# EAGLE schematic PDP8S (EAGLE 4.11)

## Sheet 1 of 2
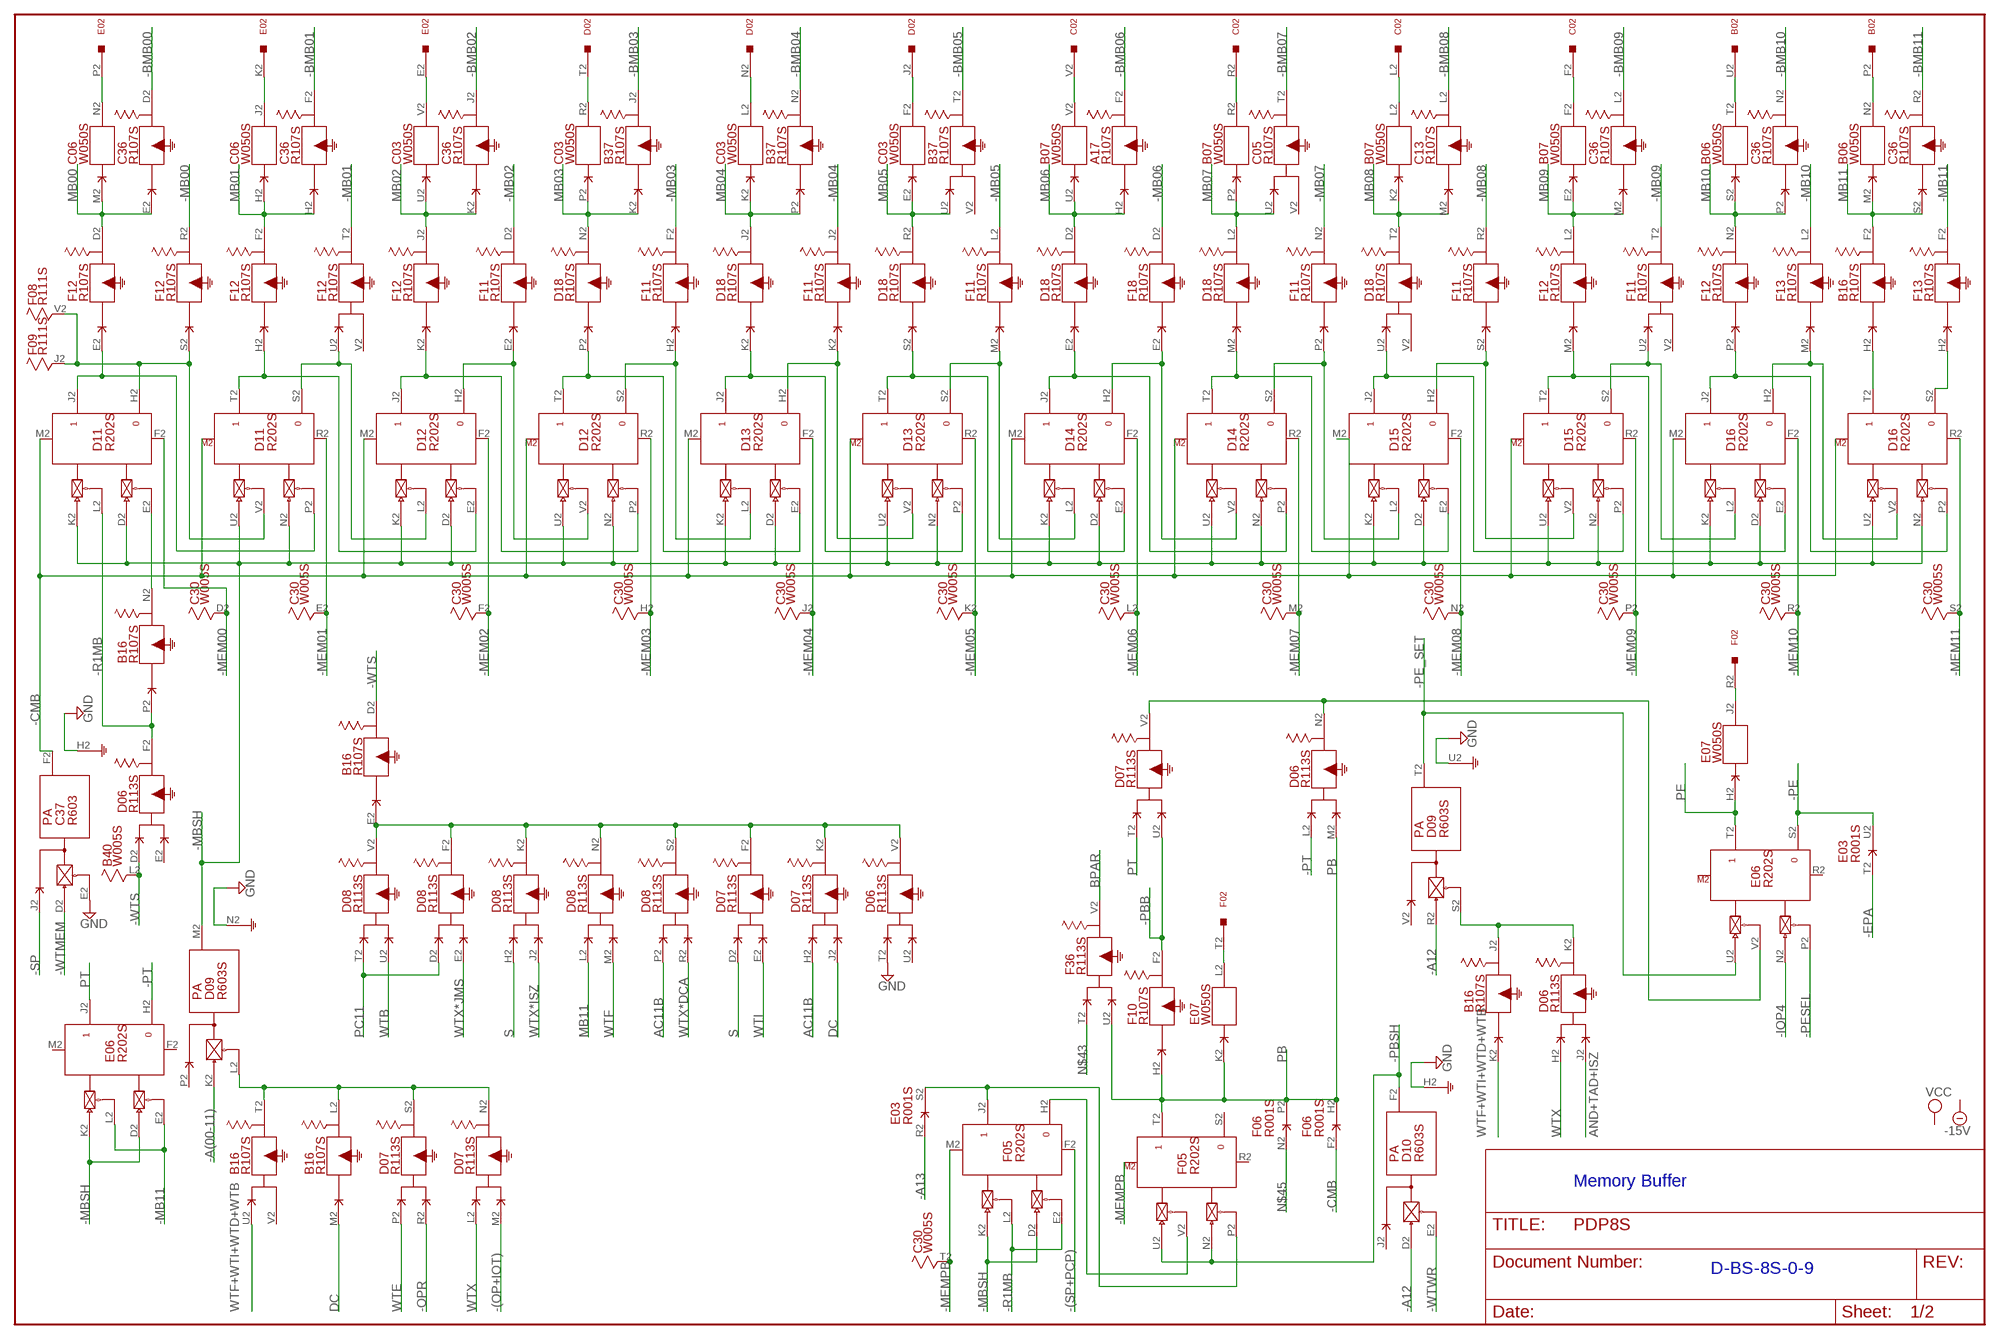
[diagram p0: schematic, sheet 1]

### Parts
A17  R107S  [H807S]
B02  W023S  [H807S]
B06  W050S  [H807S]
B07  W050S  [H807S]
B16  R107S  [H807S]
B37  R107S  [H807S]
B40  W005S  [H807S]
C02  W023S  [H807S]
C03  W050S  [H807S]
C05  R107S  [H807S]
C06  W050S  [H807S]
C13  R107S  [H807S]
C30  W005S  [H807S]
C36  R107S  [H807S]
C37  R603  [H807]
D02  W023S  [H807S]
D06  R113S  [H807S]
D07  R113S  [H807S]
D08  R113S  [H807S]
D09  R603S  [H807S]
D10  R603S  [H807S]
D11  R202S  [H807S]
D12  R202S  [H807S]
D13  R202S  [H807S]
D14  R202S  [H807S]
D15  R202S  [H807S]
D16  R202S  [H807S]
D18  R107S  [H807S]
E02  W023S  [H807S]
E03  R001S  [H807S]
E06  R202S  [H807S]
E07  W050S  [H807S]
F02  W023S  [H807S]
F05  R202S  [H807S]
F06  R001S  [H807S]
F08  R111S  [H807S]
F09  R111S  [H807S]
F10  R107S  [H807S]
F11  R107S  [H807S]
F12  R107S  [H807S]
F13  R107S  [H807S]
F18  R107S  [H807S]
F36  R113S  [H807S]

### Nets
-(OP+IOT): D07.M2(N:I$2)
-(SP+PCP): F05.F2(J:RESET)
-A12: D09.R2(T:PU0) D10.D2(F:PU0)
-A13: E03.R2(S:D)
-A(00-11): D09.K2(M:PU0)
-BMB00: C36.D2(D:O$1)
-BMB01: C36.F2(F:O$1)
-BMB02: C36.J2(J:O$1)
-BMB03: B37.J2(J:O$1)
-BMB04: B37.N2(N:O$1)
-BMB05: B37.T2(T:O$1)
-BMB06: A17.F2(F:O$1)
-BMB07: C05.T2(T:O$1)
-BMB08: C13.L2(L:O$1)
-BMB09: C36.L2(L:O$1)
-BMB10: C36.N2(N:O$1)
-BMB11: C36.R2(R:O$1)
-CMB: C37.F2(F:O) D11.M2(J:SET) D12.M2(J:SET) D13.M2(J:SET) D14.M2(J:SET) D15.M2(J:SET) D16.M2(J:SET) F06.F2(H:D)
-EPA: E03.T2(U:D)
-IOP4: E06.N2(T:PU0)
-MB00: F12.R2(R:O$1)
-MB01: F12.T2(T:O$1)
-MB02: F11.D2(D:O$1)
-MB03: F11.F2(F:O$1)
-MB04: F11.J2(J:O$1)
-MB05: F11.L2(L:O$1)
-MB06: F18.D2(D:O$1)
-MB07: F11.N2(N:O$1)
-MB08: F11.R2(R:O$1)
-MB09: F11.T2(T:O$1)
-MB10: F13.L2(L:O$1)
-MB11: E06.E2(J:EN0) E06.L2(J:EN1) F13.F2(F:O$1)
-MBSH: D09.M2(M:O) D11.D2(J:PU0) D11.K2(J:PU1) D11.N2(T:PU0) D11.U2(T:PU1) D12.D2(J:PU0) D12.K2(J:PU1) D12.N2(T:PU0) D12.U2(T:PU1) D13.D2(J:PU0) D13.K2(J:PU1) D13.N2(T:PU0) D13.U2(T:PU1) D14.D2(J:PU0) D14.K2(J:PU1) D14.N2(T:PU0) D14.U2(T:PU1) D15.D2(J:PU0) D15.K2(J:PU1) D15.N2(T:PU0) D15.U2(T:PU1) D16.D2(J:PU0) D16.K2(J:PU1) D16.N2(T:PU0) D16.U2(T:PU1) E06.D2(J:PU0) E06.K2(J:PU1) F05.D2(J:PU0) F05.K2(J:PU1)
-MEM00: C30.D2 D11.F2(J:RESET)
-MEM01: C30.E2 D11.R2(T:RESET)
-MEM02: C30.F2 D12.F2(J:RESET)
-MEM03: C30.H2 D12.R2(T:RESET)
-MEM04: C30.J2 D13.F2(J:RESET)
-MEM05: C30.K2 D13.R2(T:RESET)
-MEM06: C30.L2 D14.F2(J:RESET)
-MEM07: C30.M2 D14.R2(T:RESET)
-MEM08: C30.N2 D15.F2(J:RESET)
-MEM09: C30.P2 D15.R2(T:RESET)
-MEM10: C30.R2 D16.F2(J:RESET)
-MEM11: C30.S2 D16.R2(T:RESET)
-MEMPB: C30.T2 F05.M2(J:SET)
-OPR: D07.R2(S:I$2)
-PBB: D07.U2(V:I$2) F10.F2(F:O$1)
-PBSH: D10.F2(F:O) F05.N2(T:PU0) F05.U2(T:PU1)
-PE: E03.U2(U:E) E06.S2
-PE_SET: D09.T2(T:O) E06.U2(T:PU1)
-PESEL: E06.P2(T:EN0)
-PT: D06.L2(N:I$1) E06.H2
-R1MB: B16.P2(N:I$1) D06.F2(F:O$1) D11.L2(J:EN1) F05.E2(J:EN0) F05.L2(J:EN1)
-SP: C37.J2(F:I$1)
-WTMEM: C37.D2(F:PU0)
-WTS: B16.D2(D:O$1) B40.L2 D06.D2(F:I$1)
-WTWR: D10.E2(F:EN0)
AC11B: D07.H2(K:I$1) D08.P2(S:I$1)
AND+TAD+ISZ: D06.J2(K:I$2)
BPAR: F36.V2(V:O$1)
DC: B16.M2(L:I$1) D07.J2(K:I$2)
GND [Supply]: C37.E2(F:EN0) C37.H2(F:G) D06.T2(V:I$1) D09.N2(M:G) D09.U2(T:G) D10.H2(F:G)
MB00: C06.M2(N:I$1) C36.E2(D:I$1) F12.D2(D:O$1)
MB01: C06.H2(J:I$1) C36.H2(F:I$1) F12.F2(F:O$1)
MB02: C03.U2(V:I$1) C36.K2(J:I$1) F12.J2(J:O$1)
MB03: B37.K2(J:I$1) C03.P2(R:I$1) D18.N2(N:O$1)
MB04: B37.P2(N:I$1) C03.K2(L:I$1) D18.J2(J:O$1)
MB05: B37.U2(T:I$1) C03.E2(F:I$1) D18.R2(R:O$1)
MB06: A17.H2(F:I$1) B07.U2(V:I$1) D18.D2(D:O$1)
MB07: B07.P2(R:I$1) C05.U2(T:I$1) D18.L2(L:O$1)
MB08: B07.K2(L:I$1) C13.M2(L:I$1) D18.T2(T:O$1)
MB09: B07.E2(F:I$1) C36.M2(L:I$1) F12.L2(L:O$1)
MB10: B06.S2(T:I$1) C36.P2(N:I$1) F12.N2(N:O$1)
MB11: B06.M2(N:I$1) B16.F2(F:O$1) C36.S2(R:I$1) D08.L2(N:I$1)
N$1: D11.J2 D11.P2(T:EN0) F12.E2(D:I$1)
N$2: C06.N2(N:O$1) E02.P2
N$3: D11.H2 D11.V2(T:EN1) F08.V2 F09.J2 F12.S2(R:I$1)
N$4: D11.T2 D12.E2(J:EN0) F12.H2(F:I$1)
N$5: B16.E2(D:I$1) D06.V2(V:O$1) D07.F2(F:O$1) D07.K2(K:O$1) D08.F2(F:O$1) D08.K2(K:O$1) D08.N2(N:O$1) D08.S2(S:O$1) D08.V2(V:O$1)
N$6: D12.J2 D12.P2(T:EN0) F12.K2(J:I$1)
N$7: D12.T2 D13.E2(J:EN0) D18.P2(N:I$1)
N$8: D13.J2 D13.P2(T:EN0) D18.K2(J:I$1)
N$9: D13.T2 D14.E2(J:EN0) D18.S2(R:I$1)
N$10: D14.J2 D14.P2(T:EN0) D18.E2(D:I$1)
N$11: D14.T2 D15.E2(J:EN0) D18.M2(L:I$1)
N$12: D15.J2 D15.P2(T:EN0) D18.U2(T:I$1)
N$13: D15.H2 D15.V2(T:EN1) F11.S2(R:I$1)
N$14: D14.S2 D15.L2(J:EN1) F11.P2(N:I$1)
N$15: D14.H2 D14.V2(T:EN1) F18.E2(D:I$1)
N$16: D13.S2 D14.L2(J:EN1) F11.M2(L:I$1)
N$17: D15.T2 D16.E2(J:EN0) F12.M2(L:I$1)
N$18: D15.S2 D16.L2(J:EN1) F11.U2(T:I$1)
N$19: D16.J2 D16.P2(T:EN0) F12.P2(N:I$1)
N$20: D13.H2 D13.V2(T:EN1) F11.K2(J:I$1)
N$21: D12.S2 D13.L2(J:EN1) F11.H2(F:I$1)
N$22: D12.H2 D12.V2(T:EN1) F11.E2(D:I$1)
N$23: D11.S2 D12.L2(J:EN1) F12.U2(T:I$1)
N$24: D16.H2 D16.V2(T:EN1) F13.M2(L:I$1)
N$25: B16.H2(F:I$1) D16.T2
N$26: D16.S2 F13.H2(F:I$1)
N$27: C06.J2(J:O$1) E02.K2
N$28: C03.V2(V:O$1) E02.E2
N$29: C03.R2(R:O$1) D02.T2
N$30: C03.L2(L:O$1) D02.N2
N$31: C03.F2(F:O$1) D02.J2
N$32: B07.V2(V:O$1) C02.V2
N$33: B07.R2(R:O$1) C02.R2
N$34: B07.L2(L:O$1) C02.L2
N$35: B07.F2(F:O$1) C02.F2
N$36: B02.U2 B06.T2(T:O$1)
N$37: B02.P2 B06.N2(N:O$1)
N$38: B16.L2(L:O$1) B16.T2(T:O$1) D07.N2(N:O$1) D07.S2(S:O$1) D09.L2(M:EN0)
N$39: B16.N2(N:O$1) D11.E2(J:EN0)
N$40: B16.J2(J:O$1) D06.K2(K:O$1) D09.S2(T:EN0)
N$41: E07.J2(J:O$1) F02.R2
N$42: D06.N2(N:O$1) D07.V2(V:O$1) E06.V2(T:EN1)
N$43: F36.T2(V:I$1)
N$44: E07.L2(L:O$1) F02.T2
N$45: F06.N2(P:D)
N$46: F05.H2 F05.V2(T:EN1)
N$47: E03.S2(S:E) F05.J2 F05.P2(T:EN0)
PB: D06.M2(N:I$2) E07.K2(L:I$1) F05.T2 F06.H2(H:E) F06.P2(P:E) F10.H2(F:I$1) F36.U2(V:I$2)
PC11: D08.D2(F:I$1) D08.T2(V:I$1)
PE: E06.T2 E07.H2(J:I$1)
PT: D07.T2(V:I$1) E06.J2
S: D07.D2(F:I$1) D08.H2(K:I$1)
WTB: D08.U2(V:I$2)
WTE: D07.P2(S:I$1)
WTF: D08.M2(N:I$2)
WTF+WTI+WTD+WTB: B16.K2(J:I$1) B16.U2(T:I$1)
WTI: D07.E2(F:I$2)
WTX: D06.H2(K:I$1) D07.L2(N:I$1)
WTX*DCA: D08.R2(S:I$2)
WTX*ISZ: D08.J2(K:I$2)
WTX*JMS: D08.E2(F:I$2)
Unconnected: A17.D2(D:O$1) A17.E2(D:I$1) A17.J2(J:O$1) A17.K2(J:I$1) A17.L2(L:O$1) A17.M2(L:I$1) A17.N2(N:O$1) A17.P2(N:I$1) A17.R2(R:O$1) A17.S2(R:I$1) A17.T2(T:O$1) A17.U2(T:I$1) A17.V2(T:I$2) B02.A2 B02.B2 B02.C2 B02.D2 B02.E2 B02.F2 B02.H2 B02.J2 B02.K2 B02.L2 B02.M2 B02.N2 B02.R2 B02.S2 B02.T2 B02.V2 B06.E2(F:I$1) B06.F2(F:O$1) B06.H2(J:I$1) B06.J2(J:O$1) B06.K2(L:I$1) B06.L2(L:O$1) B06.P2(R:I$1) B06.R2(R:O$1) B06.U2(V:I$1) B06.V2(V:O$1) B07.H2(J:I$1) B07.J2(J:O$1) B07.M2(N:I$1) B07.N2(N:O$1) B07.S2(T:I$1) B07.T2(T:O$1) B16.R2(R:O$1) B16.S2(R:I$1) B16.V2(T:I$2) B37.D2(D:O$1) B37.E2(D:I$1) B37.F2(F:O$1) B37.H2(F:I$1) B37.L2(L:O$1) B37.M2(L:I$1) B37.R2(R:O$1) B37.S2(R:I$1) B37.V2(T:I$2) B40.D2 B40.E2 B40.F2 B40.H2 B40.J2 B40.K2 B40.M2 B40.N2 B40.P2 B40.R2 B40.S2 B40.T2 B40.U2 B40.V2 C02.A2 C02.B2 C02.C2 C02.D2 C02.E2 C02.H2 C02.J2 C02.K2 C02.M2 C02.N2 C02.P2 C02.S2 C02.T2 C02.U2 C03.H2(J:I$1) C03.J2(J:O$1) C03.M2(N:I$1) C03.N2(N:O$1) C03.S2(T:I$1) C03.T2(T:O$1) C05.D2(D:O$1) C05.E2(D:I$1) C05.F2(F:O$1) C05.H2(F:I$1) C05.J2(J:O$1) C05.K2(J:I$1) C05.L2(L:O$1) C05.M2(L:I$1) C05.N2(N:O$1) C05.P2(N:I$1) C05.R2(R:O$1) C05.S2(R:I$1) C05.V2(T:I$2) C06.E2(F:I$1) C06.F2(F:O$1) C06.K2(L:I$1) C06.L2(L:O$1) C06.P2(R:I$1) C06.R2(R:O$1) C06.S2(T:I$1) C06.T2(T:O$1) C06.U2(V:I$1) C06.V2(V:O$1) C13.D2(D:O$1) C13.E2(D:I$1) C13.F2(F:O$1) C13.H2(F:I$1) C13.J2(J:O$1) C13.K2(J:I$1) C13.N2(N:O$1) C13.P2(N:I$1) C13.R2(R:O$1) C13.S2(R:I$1) C13.T2(T:O$1) C13.U2(T:I$1) C13.V2(T:I$2) C30.U2 C30.V2 C36.T2(T:O$1) C36.U2(T:I$1) C36.V2(T:I$2) C37.K2(M:PU0) C37.L2(M:EN0) C37.M2(M:O) C37.N2(M:G) C37.P2(M:I$1) C37.R2(T:PU0) C37.S2(T:EN0) C37.T2(T:O) C37.U2(T:G) C37.V2(T:I$1) D02.A2 D02.B2 D02.C2 D02.D2 D02.E2 D02.F2 D02.H2 D02.K2 D02.L2 D02.M2 D02.P2 D02.R2 D02.S2 D02.U2 D02.V2 D06.E2(F:I$2) D06.P2(S:I$1) D06.R2(S:I$2) D06.S2(S:O$1) D06.U2(V:I$2) D09.D2(F:PU0) D09.E2(F:EN0) D09.F2(F:O) D09.H2(F:G) D09.J2(F:I$1) D09.P2(M:I$1) D09.V2(T:I$1) D10.J2(F:I$1) D10.K2(M:PU0) D10.L2(M:EN0) D10.M2(M:O) D10.N2(M:G) D10.P2(M:I$1) D10.R2(T:PU0) D10.S2(T:EN0) D10.T2(T:O) D10.U2(T:G) D10.V2(T:I$1) D18.F2(F:O$1) D18.H2(F:I$1) D18.V2(T:I$2) E02.A2 E02.B2 E02.C2 E02.D2 E02.F2 E02.H2 E02.J2 E02.L2 E02.M2 E02.N2 E02.R2 E02.S2 E02.T2 E02.U2 E02.V2 E03.D2(E:D) E03.E2(E:E) E03.F2(H:D) E03.H2(H:E) E03.J2(K:D) E03.K2(K:E) E03.L2(M:D) E03.M2(M:E) E03.N2(P:D) E03.P2(P:E) E06.F2(J:RESET) E06.M2(J:SET) E06.R2(T:RESET) E07.E2(F:I$1) E07.F2(F:O$1) E07.M2(N:I$1) E07.N2(N:O$1) E07.P2(R:I$1) E07.R2(R:O$1) E07.S2(T:I$1) E07.T2(T:O$1) E07.U2(V:I$1) E07.V2(V:O$1) F02.A2 F02.B2 F02.C2 F02.D2 F02.E2 F02.F2 F02.H2 F02.J2 F02.K2 F02.L2 F02.M2 F02.N2 F02.P2 F02.S2 F02.U2 F02.V2 F05.R2(T:RESET) F05.S2 F06.D2(E:D) F06.E2(E:E) F06.J2(K:D) F06.K2(K:E) F06.L2(M:D) F06.M2(M:E) F06.R2(S:D) F06.S2(S:E) F06.T2(U:D) F06.U2(U:E) F08.D2(H:I$1) F08.E2(H:I$2) F08.F2(H:I$3) F08.H2(H:O$1) F08.J2 F08.K2(N:I$1) F08.L2(N:I$2) F08.M2(N:I$3) F08.N2(N:O$1) F08.P2 F08.R2(U:I$1) F08.S2(U:I$2) F08.T2(U:I$3) F08.U2(U:O$1) F09.D2(H:I$1) F09.E2(H:I$2) F09.F2(H:I$3) F09.H2(H:O$1) F09.K2(N:I$1) F09.L2(N:I$2) F09.M2(N:I$3) F09.N2(N:O$1) F09.P2 F09.R2(U:I$1) F09.S2(U:I$2) F09.T2(U:I$3) F09.U2(U:O$1) F09.V2 F10.D2(D:O$1) F10.E2(D:I$1) F10.J2(J:O$1) F10.K2(J:I$1) F10.L2(L:O$1) F10.M2(L:I$1) F10.N2(N:O$1) F10.P2(N:I$1) F10.R2(R:O$1) F10.S2(R:I$1) F10.T2(T:O$1) F10.U2(T:I$1) F10.V2(T:I$2) F11.V2(T:I$2) F12.V2(T:I$2) F13.D2(D:O$1) F13.E2(D:I$1) F13.J2(J:O$1) F13.K2(J:I$1) F13.N2(N:O$1) F13.P2(N:I$1) F13.R2(R:O$1) F13.S2(R:I$1) F13.T2(T:O$1) F13.U2(T:I$1) F13.V2(T:I$2) F18.F2(F:O$1) F18.H2(F:I$1) F18.J2(J:O$1) F18.K2(J:I$1) F18.L2(L:O$1) F18.M2(L:I$1) F18.N2(N:O$1) F18.P2(N:I$1) F18.R2(R:O$1) F18.S2(R:I$1) F18.T2(T:O$1) F18.U2(T:I$1) F18.V2(T:I$2) F36.D2(F:I$1) F36.E2(F:I$2) F36.F2(F:O$1) F36.H2(K:I$1) F36.J2(K:I$2) F36.K2(K:O$1) F36.L2(N:I$1) F36.M2(N:I$2) F36.N2(N:O$1) F36.P2(S:I$1) F36.R2(S:I$2) F36.S2(S:O$1)

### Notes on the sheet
- Memory Buffer
- D-BS-8S-0-9

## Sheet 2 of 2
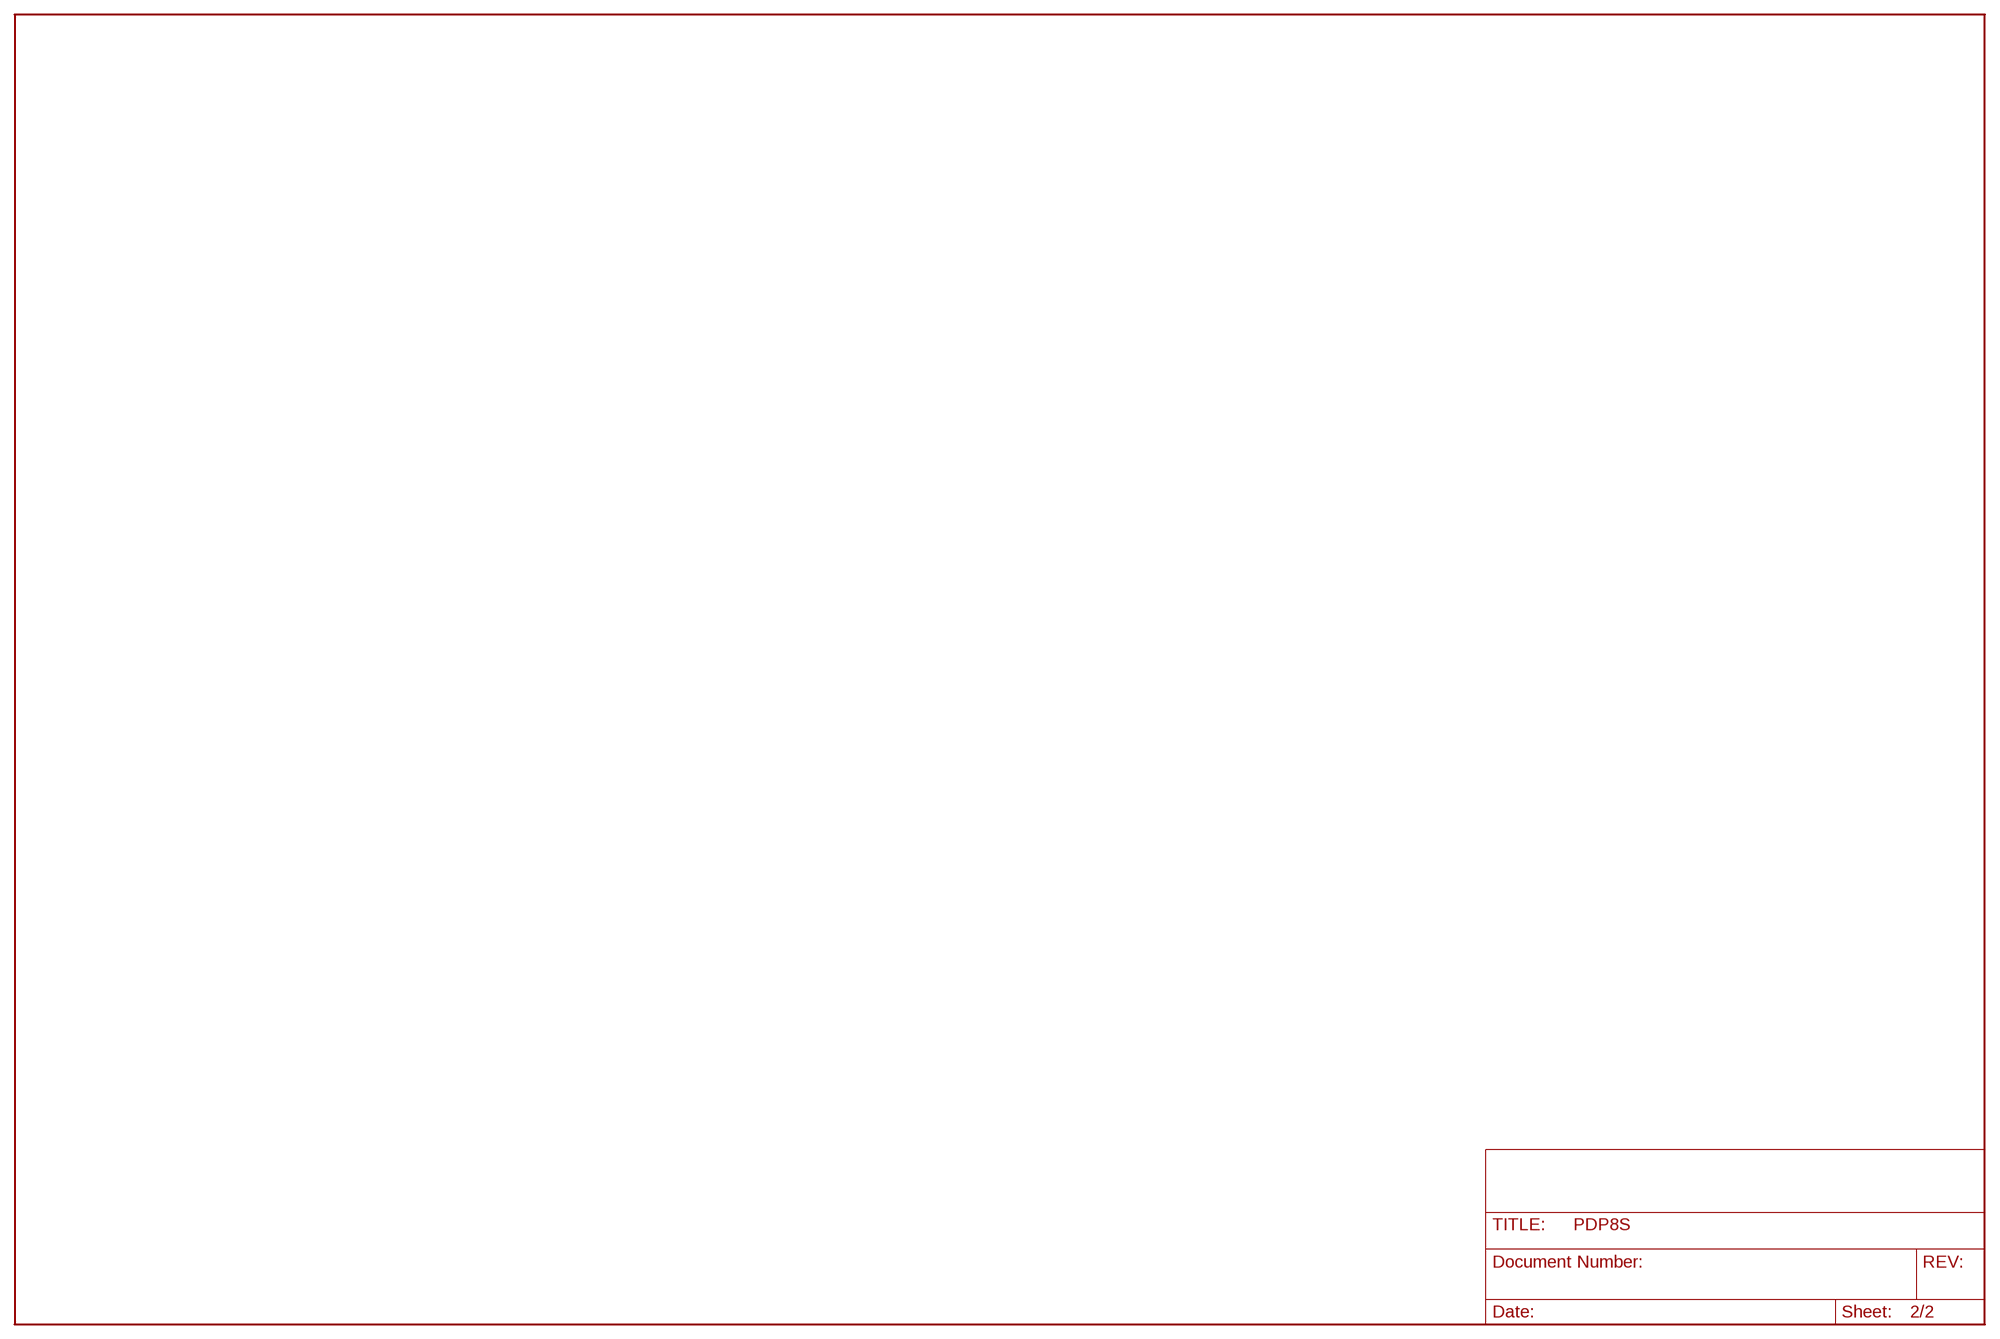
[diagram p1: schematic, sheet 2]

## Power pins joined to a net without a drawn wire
-15V: A17.B2(-15V) B06.B2(-15V) B07.B2(-15V) B16.B2(-15V) B37.B2(-15V) B40.B2(-15V) C03.B2(-15V) C05.B2(-15V) C06.B2(-15V) C13.B2(-15V) C30.B2(-15V) C36.B2(-15V) C37.B2(-15V) D06.B2(-15V) D07.B2(-15V) D08.B2(-15V) D09.B2(-15V) D10.B2(-15V) D11.B2(-15V) D12.B2(-15V) D13.B2(-15V) D14.B2(-15V) D15.B2(-15V) D16.B2(-15V) D18.B2(-15V) E03.B2(-15V) E06.B2(-15V) E07.B2(-15V) F05.B2(-15V) F06.B2(-15V) F08.B2(-15V) F09.B2(-15V) F10.B2(-15V) F11.B2(-15V) F12.B2(-15V) F13.B2(-15V) F18.B2(-15V) F36.B2(-15V)
GND: A17.C2(GND) B06.C2(GND) B07.C2(GND) B16.C2(GND) B37.C2(GND) B40.C2(GND) C03.C2(GND) C05.C2(GND) C06.C2(GND) C13.C2(GND) C30.C2(GND) C36.C2(GND) C37.C2(GND) D06.C2(GND) D07.C2(GND) D08.C2(GND) D09.C2(GND) D10.C2(GND) D11.C2(GND) D12.C2(GND) D13.C2(GND) D14.C2(GND) D15.C2(GND) D16.C2(GND) D18.C2(GND) E03.C2(GND) E06.C2(GND) E07.C2(GND) F05.C2(GND) F06.C2(GND) F08.C2(GND) F09.C2(GND) F10.C2(GND) F11.C2(GND) F12.C2(GND) F13.C2(GND) F18.C2(GND) F36.C2(GND)
VCC: A17.A2(VCC) B06.A2(VCC) B07.A2(VCC) B16.A2(VCC) B37.A2(VCC) B40.A2(VCC) C03.A2(VCC) C05.A2(VCC) C06.A2(VCC) C13.A2(VCC) C30.A2(VCC) C36.A2(VCC) C37.A2(VCC) D06.A2(VCC) D07.A2(VCC) D08.A2(VCC) D09.A2(VCC) D10.A2(VCC) D11.A2(VCC) D12.A2(VCC) D13.A2(VCC) D14.A2(VCC) D15.A2(VCC) D16.A2(VCC) D18.A2(VCC) E03.A2(VCC) E06.A2(VCC) E07.A2(VCC) F05.A2(VCC) F06.A2(VCC) F08.A2(VCC) F09.A2(VCC) F10.A2(VCC) F11.A2(VCC) F12.A2(VCC) F13.A2(VCC) F18.A2(VCC) F36.A2(VCC)

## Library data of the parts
A17 B16 B37 C05 C13 C36 D18 F10-F13 F18 = dec-r:R107: 7 Inverters
B02 C02 D02 E02 F02 = dec-r:W023: One-sided 18 pin connector/cable.
B06 B07 C03 C06 E07 = dec-r:W050: Indicator Driver
B40 C30 = dec-r:W005: 15 Clamped Loads
C37 D09 D10 = dec-r:R603: Triple Pulse Amplifier
D06-D08 F36 = dec-r:R113: Diode Gate
D11-D16 E06 F05 = dec-r:R202: Dual Flip-Flop
E03 F06 = dec-r:R001: 7 Diodes
F08 F09 = dec-r:R111: Diode Gate

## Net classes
1 Supply: width 0.635 mm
